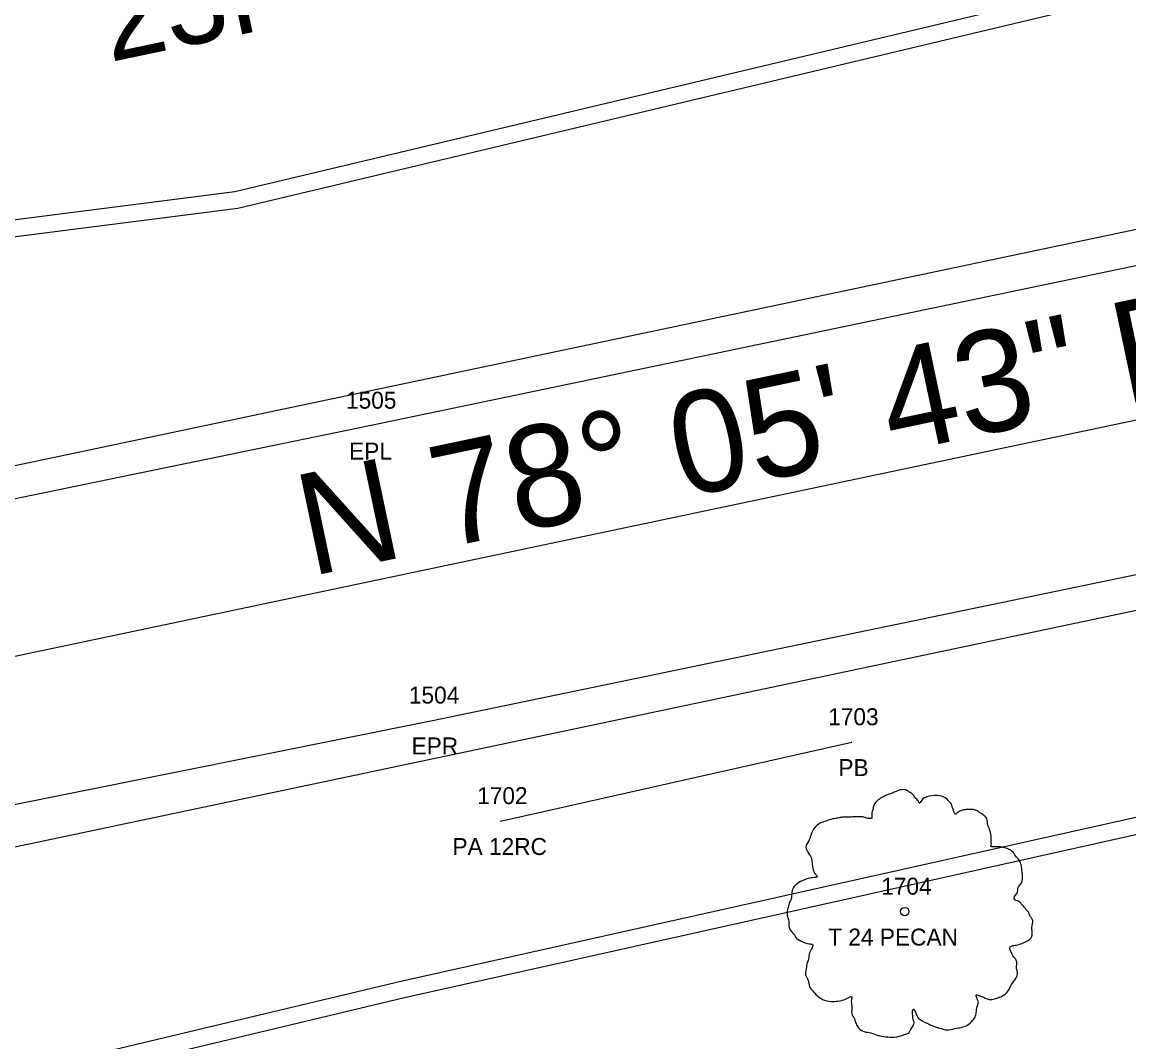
# Model space of a CAD drawing. Extents: x 1964982 to 1970452, y 1116335 to 1119906.
# Drawn here: x 1966510.7 to 1966576, y 1117362.4 to 1117422.5 of the extents above; entities that cross this region are included whole.
import ezdxf

# ---------------------------------------------------------------- set-up
doc = ezdxf.new("R2010")
doc.units = 0
for name, color, linetype in [('RD_EX_DR_Pipe', 7, 'Continuous'), ('RD_EX_DR_Pipe_txCode', 7, 'Continuous'), ('RD_EX_DV_Prop', 7, 'Continuous'), ('RD_EX_Road', 7, 'Continuous'), ('RD_EX_Road_txCode', 7, 'Continuous'), ('RD_EX_RW', 7, 'Continuous'), ('RD_EX_VEG', 7, 'Continuous'), ('RD_EX_VEG_txCode', 7, 'Continuous'), ('RD_HC_CL', 7, 'Continuous'), ('RD_HC_Data', 7, 'Continuous'), ('RD_PD_CstnLmt', 7, 'Continuous'), ('RD_PD_Final_TrvlWay', 7, 'Continuous'), ('RD_PD_RW', 7, 'Continuous'), ('RD_PD_TX_CstnLmt', 7, 'Continuous'), ('RD_SMD_Locator', 7, 'Continuous')]:
    doc.layers.add(name, color=color, linetype=linetype)

msp = doc.modelspace()

# ---------------------------------------------------------------- linework, layer by layer
at = {"layer": 'RD_EX_DR_Pipe'}
msp.add_line((1966538.934, 1117375.409), (1966559.639, 1117380.064), dxfattribs=at)
at = {"layer": 'RD_EX_DV_Prop'}
msp.add_line((1966425.261, 1117367.215), (1966684.872, 1117421.945), dxfattribs=at)
at = {"layer": 'RD_EX_Road'}
for points in [[(1966297.245, 1117343.102), (1966344.085, 1117357.038), (1966390.785, 1117368.561), (1966438.122, 1117379.082), (1966484.547, 1117389.131), (1966531.199, 1117398.733), (1966578.388, 1117408.593), (1966604.527, 1117414.058), (1966624.537, 1117418.323), (1966671.319, 1117428.348), (1966716.506, 1117439.32), (1966736.604, 1117445.59), (1966754.133, 1117451.442), (1966759.658, 1117453.517), (1966769.512, 1117457.475)], [(1965729.992, 1117080.297), (1965819.77, 1117119.134), (1965907.737, 1117159.312), (1965995.365, 1117199.039), (1966039.268, 1117218.497), (1966081.241, 1117237.148), (1966124.665, 1117256.555), (1966167.659, 1117275.555), (1966211.467, 1117293.627), (1966257.791, 1117311.581), (1966302.7, 1117327.207), (1966347.903, 1117339.982), (1966394.806, 1117351.637), (1966441.557, 1117361.865), (1966488.625, 1117372.057), (1966534.906, 1117381.34), (1966581.234, 1117390.947), (1966629.533, 1117400.947), (1966675.632, 1117411.107), (1966721.676, 1117422.847), (1966766.802, 1117438.972), (1966775.751, 1117440.571)]]:
    msp.add_lwpolyline(points, dxfattribs=at)
at = {"layer": 'RD_EX_RW'}
for points in [[(1966297.245, 1117343.102), (1966344.085, 1117357.038), (1966390.785, 1117368.561), (1966438.122, 1117379.082), (1966484.547, 1117389.131), (1966531.199, 1117398.733), (1966578.388, 1117408.593), (1966604.527, 1117414.058), (1966624.537, 1117418.323), (1966671.319, 1117428.348), (1966716.506, 1117439.32), (1966736.604, 1117445.59), (1966754.133, 1117451.442), (1966759.658, 1117453.517), (1966769.512, 1117457.475)], [(1965729.992, 1117080.297), (1965819.77, 1117119.134), (1965907.737, 1117159.312), (1965995.365, 1117199.039), (1966039.268, 1117218.497), (1966081.241, 1117237.148), (1966124.665, 1117256.555), (1966167.659, 1117275.555), (1966211.467, 1117293.627), (1966257.791, 1117311.581), (1966302.7, 1117327.207), (1966347.903, 1117339.982), (1966394.806, 1117351.637), (1966441.557, 1117361.865), (1966488.625, 1117372.057), (1966534.906, 1117381.34), (1966581.234, 1117390.947), (1966629.533, 1117400.947), (1966675.632, 1117411.107), (1966721.676, 1117422.847), (1966766.802, 1117438.972), (1966775.751, 1117440.571)]]:
    msp.add_lwpolyline(points, dxfattribs=at)
at = {"layer": 'RD_EX_VEG'}
for centre, radius in [((1966562.766, 1117370.068), 0.25), ((1966562.753, 1117370.05), 0.0001)]:
    msp.add_circle(centre, radius, dxfattribs=at)
for points in [[(1966562.897, 1117377.236), (1966562.598, 1117377.261), (1966562.273, 1117377.161), (1966562.023, 1117377.061), (1966561.798, 1117376.986), (1966561.573, 1117376.886), (1966561.273, 1117376.711), (1966561.048, 1117376.511), (1966560.923, 1117376.261), (1966560.873, 1117376.036), (1966560.823, 1117375.761), (1966560.823, 1117375.586), (1966560.698, 1117375.561), (1966560.548, 1117375.586), (1966560.299, 1117375.661), (1966560.049, 1117375.661), (1966559.799, 1117375.661), (1966559.449, 1117375.636), (1966559.099, 1117375.636), (1966558.824, 1117375.586), (1966558.499, 1117375.536), (1966558.125, 1117375.411), (1966557.775, 1117375.286), (1966557.475, 1117375.037), (1966557.225, 1117374.562), (1966557.1, 1117374.212), (1966556.95, 1117373.962), (1966557.1, 1117373.512), (1966557.275, 1117373.162), (1966557.3, 1117372.962), (1966557.375, 1117372.538), (1966557.475, 1117372.313), (1966557.6, 1117372.113), (1966557.525, 1117372.088), (1966557.15, 1117372.038), (1966556.85, 1117371.938), (1966556.425, 1117371.713), (1966556.2, 1117371.488), (1966556.1, 1117371.163), (1966556.075, 1117370.813), (1966555.976, 1117370.614), (1966555.901, 1117370.339), (1966555.876, 1117370.264), (1966555.826, 1117369.939), (1966555.926, 1117369.489), (1966555.951, 1117369.139), (1966556.075, 1117368.914), (1966556.225, 1117368.739), (1966556.4, 1117368.489), (1966556.8, 1117368.265), (1966557.125, 1117368.165), (1966557.325, 1117368.14), (1966557.15, 1117367.64), (1966557.1, 1117367.29), (1966556.975, 1117366.89), (1966556.975, 1117366.815), (1966556.925, 1117366.34), (1966557.075, 1117366.015), (1966557.15, 1117365.641), (1966557.325, 1117365.416), (1966557.6, 1117365.116), (1966557.925, 1117364.891), (1966558.424, 1117364.766), (1966558.824, 1117364.791), (1966559.399, 1117364.966), (1966559.649, 1117365.041), (1966559.624, 1117364.866), (1966559.649, 1117364.491), (1966559.649, 1117364.066), (1966559.799, 1117363.742), (1966559.899, 1117363.467), (1966560.049, 1117363.217), (1966560.374, 1117362.992), (1966560.773, 1117362.917), (1966561.198, 1117362.767), (1966561.648, 1117362.692), (1966562.148, 1117362.667), (1966562.748, 1117362.817), (1966563.022, 1117362.942), (1966563.122, 1117363.117), (1966563.322, 1117363.492), (1966563.272, 1117363.717), (1966563.297, 1117364.316), (1966563.397, 1117364.141), (1966563.572, 1117363.791), (1966564.072, 1117363.492), (1966564.472, 1117363.317), (1966564.947, 1117363.167), (1966565.246, 1117363.092), (1966565.721, 1117363.167), (1966566.096, 1117363.242), (1966566.471, 1117363.367), (1966566.771, 1117363.642), (1966566.946, 1117363.916), (1966566.996, 1117364.191), (1966567.071, 1117364.566), (1966567.121, 1117364.741)], [(1966567.121, 1117364.741), (1966567.046, 1117364.916), (1966566.996, 1117365.166), (1966567.071, 1117365.141), (1966567.246, 1117365.091), (1966567.52, 1117364.966), (1966567.745, 1117364.891), (1966568.07, 1117364.916), (1966568.345, 1117365.016), (1966568.795, 1117365.291), (1966569.07, 1117365.766), (1966569.345, 1117366.165), (1966569.42, 1117366.49), (1966569.37, 1117366.715), (1966569.345, 1117367.215), (1966569.145, 1117367.465), (1966569.095, 1117367.59), (1966568.995, 1117367.99), (1966569.07, 1117368.04), (1966569.345, 1117368.09), (1966569.719, 1117368.215), (1966569.994, 1117368.339), (1966570.219, 1117368.514), (1966570.294, 1117368.739), (1966570.269, 1117369.139), (1966570.319, 1117369.539), (1966570.244, 1117369.689), (1966570.144, 1117369.839), (1966570.069, 1117370.039), (1966569.919, 1117370.189), (1966569.819, 1117370.339), (1966569.719, 1117370.439), (1966569.595, 1117370.589), (1966569.42, 1117370.713), (1966569.27, 1117370.763), (1966569.22, 1117370.913), (1966569.37, 1117371.113), (1966569.42, 1117371.213), (1966569.445, 1117371.438), (1966569.67, 1117371.788), (1966569.719, 1117372.188), (1966569.67, 1117372.613), (1966569.62, 1117372.888), (1966569.47, 1117373.162), (1966569.27, 1117373.412), (1966569.145, 1117373.587), (1966568.97, 1117373.712), (1966568.645, 1117373.837), (1966568.395, 1117373.887), (1966568.045, 1117373.887), (1966567.845, 1117373.937), (1966567.87, 1117373.987), (1966567.87, 1117374.137), (1966567.87, 1117374.412), (1966567.795, 1117374.862), (1966567.645, 1117375.361), (1966567.645, 1117375.386), (1966567.545, 1117375.636), (1966567.321, 1117375.836), (1966567.146, 1117375.936), (1966566.946, 1117376.061), (1966566.696, 1117376.086), (1966566.396, 1117376.086), (1966566.121, 1117376.036), (1966565.921, 1117375.936), (1966565.746, 1117375.811), (1966565.671, 1117375.961), (1966565.571, 1117376.261), (1966565.521, 1117376.411), (1966565.371, 1117376.586), (1966565.147, 1117376.786), (1966564.697, 1117376.911), (1966564.072, 1117376.836), (1966563.772, 1117376.636), (1966563.622, 1117376.461), (1966563.572, 1117376.586), (1966563.372, 1117376.786), (1966563.272, 1117376.961), (1966563.097, 1117377.086), (1966562.947, 1117377.186), (1966562.847, 1117377.236)]]:
    msp.add_spline(points, degree=3, dxfattribs=at)
at = {"layer": 'RD_HC_CL'}
msp.add_line((1966425.261, 1117367.215), (1966684.871, 1117421.945), dxfattribs=at)
at = {"layer": 'RD_PD_CstnLmt'}
for p, q in [((1966572.088, 1117423.122), (1966523.43, 1117411.54)), ((1966523.43, 1117411.54), (1966473.667, 1117405.202)), ((1966581.847, 1117376.829), (1966533.041, 1117365.953)), ((1966533.041, 1117365.953), (1966484.385, 1117354.365))]:
    msp.add_line(p, q, dxfattribs=at)
at = {"layer": 'RD_PD_Final_TrvlWay'}
for p, q in [((1966422.992, 1117377.978), (1966607.856, 1117416.951)), ((1966427.53, 1117356.451), (1966612.394, 1117395.424))]:
    msp.add_line(p, q, dxfattribs=at)
at = {"layer": 'RD_PD_RW'}
for p, q in [((1966571.829, 1117424.088), (1966523.251, 1117412.525)), ((1966523.251, 1117412.525), (1966473.507, 1117406.189)), ((1966582.056, 1117375.851), (1966533.265, 1117364.979)), ((1966533.265, 1117364.979), (1966484.62, 1117353.393))]:
    msp.add_line(p, q, dxfattribs=at)
at = {"layer": 'RD_SMD_Locator'}
for centre in [(1966531.199, 1117398.733), (1966531.199, 1117398.733), (1966534.906, 1117381.34), (1966534.906, 1117381.34), (1966559.639, 1117380.064), (1966538.934, 1117375.409)]:
    msp.add_circle(centre, 0.001, dxfattribs=at)

# ---------------------------------------------------------------- texts
at = {"layer": 'RD_EX_DR_Pipe_txCode'}
for s, p in [('1703', (1966558.253, 1117381.064)), ('PB', (1966558.859, 1117378.064)), ('1702', (1966537.548, 1117376.409)), ('PA 12RC', (1966536.092, 1117373.409))]:
    msp.add_text(s, height=1, dxfattribs=at).set_placement(p)
at = {"layer": 'RD_EX_Road_txCode'}
for s, p in [('1505', (1966529.813, 1117399.733)), ('1505', (1966529.813, 1117399.733)), ('EPL', (1966529.994, 1117396.733)), ('EPL', (1966529.994, 1117396.733)), ('1504', (1966533.52, 1117382.34)), ('1504', (1966533.52, 1117382.34)), ('EPR', (1966533.677, 1117379.34)), ('EPR', (1966533.677, 1117379.34))]:
    msp.add_text(s, height=1, dxfattribs=at).set_placement(p)
at = {"layer": 'RD_EX_VEG_txCode'}
for s, p in [('1704', (1966561.38, 1117371.068)), ('T 24 PECAN', (1966558.254, 1117368.068))]:
    msp.add_text(s, height=1, dxfattribs=at).set_placement(p)
at = {"layer": 'RD_HC_Data'}
msp.add_text('N 78° 05\' 43" E', height=6, rotation=11.90472, dxfattribs=at).set_placement((1966527.716, 1117389.836))
at = {"layer": 'RD_PD_TX_CstnLmt'}
msp.add_text('23F', height=5, rotation=11.90472, dxfattribs=at).set_placement((1966515.876, 1117420.167))

doc.saveas('drawing.dxf')
